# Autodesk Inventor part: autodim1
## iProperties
Author: Administrator
Created: 2000-12
Part Number: autodim1
Document SubType Name: Modeling
Designer: Administrator
Control State: 0
Master: False
Checked Out: False
PropertySet Name: Design Tracking Control
Shininess: 0.0
PropertySet Name: _Private Model Information
Density: 0.0
Volumn: 0.0
Area: 0.0
PropertySet Name: Model Information
